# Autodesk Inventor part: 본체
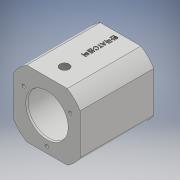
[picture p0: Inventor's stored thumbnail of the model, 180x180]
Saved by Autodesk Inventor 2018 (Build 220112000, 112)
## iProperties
Created: 2020-02
Part Number: 본체
Material: 일반
Document SubType Name: Modeling
Designer: USER
Density: 1 g/cm^3
Appearance: 기본값
Mass: 199.219 g
Surface Area: 342.742 cm^2
Volume: 199.219 cm^3
Author: USER
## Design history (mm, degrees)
sketch "스케치1"
  geometry: L1 (32, -32)-(-32, -32); L2 (-32, -32)-(-32, 32); L3 (-32, 32)-(32, 32); L4 (32, 32)-(32, -32); L5 (32, -32)-(-32, 32); L6 (-32, -32)-(32, 32); 1 further point
  constraints: 12 end point, 2 midpoint, 2 parallel, 1 horizontal, 1 perpendicular
  dimensions: "d0" = 64 distance of L2.end L3.end; "d1" = 64 distance of L1.end L2.end
extrude "돌출1" new body sketch "스케치1" distance "d2" = 71; taper "d3" = 0 deg
sketch "스케치2"
  geometry: C1 r 37.5 at (0, 0); 1 further point
  constraints: 1 centre point, 1 coincident
  dimensions: "d4" = 75 diameter of C1
extrude "돌출2" sketch "스케치2" distance "d5" = 71; taper "d6" = 0 deg
sketch "스케치4"
  geometry: C1 r 14 at (0, 0); 1 further point
  constraints: 1 centre point, 1 coincident
  dimensions: "d7" = 28 diameter of C1
extrude "돌출3" join sketch "스케치4" distance "d8" = 12; taper "d9" = 0 deg
sketch "스케치5"
  geometry: C1 r 20 at (0, 0); 1 further point
  constraints: 1 centre point, 1 coincident
  dimensions: "d10" = 40 diameter of C1
extrude "돌출4" cut sketch "스케치5" distance "d11" = 62; taper "d12" = 0 deg
sketch "스케치6"
  geometry: 2 further points
  constraints: 1 coincident
hole "구멍1" sketch "스케치6" at (0, 0) diameter "d13" = 8.917; stored, may be unused: countersink angle "d17" = 90 deg, drill point angle "d19" = 118 deg; dims "d14" = 14, "d15" = 4, "d16" = 2, "d18" = 17
sketch "스케치7"
  geometry: C1 r 2 at (0, 0); 1 further point
  constraints: 1 centre point, 1 coincident
  dimensions: "d20" = 4 diameter of C1
extrude "돌출5" cut sketch "스케치7" distance "d21" = 62; taper "d22" = 0 deg
sketch "스케치8"
  geometry: L1 (0, 0)-(-22.517, 13); L2 (0, 0)-(0, 32); L3 (-19.551, 32)-(19.551, 32) reference; L4 (0, 0)-(22.517, 13); C1 r 2 at (0, 0) reference; A1 r 26 centre (0, 0) between (-22.517, 13) and (0, -26); 2 further points
  constraints: 6 end point, 2 coincident, 2 point on circle, 1 centre point, 1 midpoint, 1 symmetric about line
  dimensions: "d23" = 52 diameter of A1; "d24" = 60 deg angle of L2 L1
hole "구멍2" sketch "스케치8" at (-22.517, 13), (22.517, 13), (0, -26) diameter "d25" = 3.242; stored, may be unused: countersink angle "d29" = 90 deg, drill point angle "d31" = 118 deg; dims "d26" = 10, "d27" = 4, "d28" = 2, "d30" = 12
sketch "스케치9"
  geometry: A1 r 26 centre (0, 0) between (0, -26) and (-26, 0); 3 further points
  constraints: 4 point on circle, 1 centre point, 1 coincident
  dimensions: "d32" = 52 diameter of A1
hole "구멍3" sketch "스케치9" at (0, -26), (-26, 0), (0, 26), (26, 0) diameter "d33" = 3.242; stored, may be unused: countersink angle "d37" = 90 deg, drill point angle "d39" = 118 deg; dims "d34" = 10, "d35" = 4, "d36" = 2, "d38" = 12
sketch "스케치10"
  geometry: L1 (39.102, 71)-(51.551, 71) reference; L2 (39.102, 0)-(0, 0) reference; 3 further points
  constraints: 1 midpoint, 1 vertical alignment, 1 other
  dimensions: "d40" = 20 distance from line of L1 point (19.551, 51)
feature "엠보싱1" sketch "스케치10" dims "d0" = 64, "d1" = 64, "d41" = 0.5, "d42" = 0
sketch "스케치11"
  geometry: L1 (39.102, 0)-(0, 0) reference; 3 further points
  constraints: 1 midpoint, 1 vertical alignment
  dimensions: "d43" = 17 distance of point (19.551, 0) point (19.551, 17)
hole "구멍4" sketch "스케치11" at (19.551, 17) diameter "d44" = 8.917; stored, may be unused: countersink angle "d48" = 90 deg, drill point angle "d50" = 118 deg; dims "d45" = 6, "d46" = 4, "d47" = 2, "d49" = 9
sketch "스케치12"
  geometry: C1 r 4.458 at (19.551, 17) reference; C2 r 2 at (19.551, 17); 1 further point
  constraints: 1 centre point, 1 coincident
  dimensions: "d51" = 4 diameter of C2
extrude "돌출6" cut sketch "스케치12" distance "d52" = 20; taper "d53" = 0 deg
chamfer "모따기2" distance "d57" = 1.8; stored, may be unused: second distance "d58" = 2, angle "d59" = 15 deg
chamfer "모따기3" distance "d60" = 1; stored, may be unused: second distance "d61" = 2, angle "d62" = 15 deg
node "솔리드1"
